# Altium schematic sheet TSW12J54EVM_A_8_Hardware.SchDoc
size 431 x 279 mm; Date: Not shown in title block; ApprovedBy: Not shown in title block; CheckedBy: Not shown in title block; Author: Not shown in title block; CompanyName: Not shown in title block; Engineer: Not shown in title block; Organization: Not shown in title block; Address1: Not shown in title block; Address2: Not shown in title block; Address3: Not shown in title block; Address4: Not shown in title block; DocumentNumber: 8; Revision: Use project parameter SCH_Rev; SheetNumber: 8; SheetTotal: 8; PageSetup: Record=PageOptions¦CenterHorizontal=True¦CenterVertical=True¦PrintScale=1.00¦XCorrection=1.00¦YCorrection=1.00¦PrintKind=0¦BorderSize=5000000¦LeftOffset=0¦BottomOffset=0¦Orientation=2¦PaperLength=1000¦PaperWidth=1000¦Scale=100¦PaperSource=15¦PrintQuality=600¦MediaType=1¦DitherType=10¦PaperKind=Letter¦PrintScaleMode=1
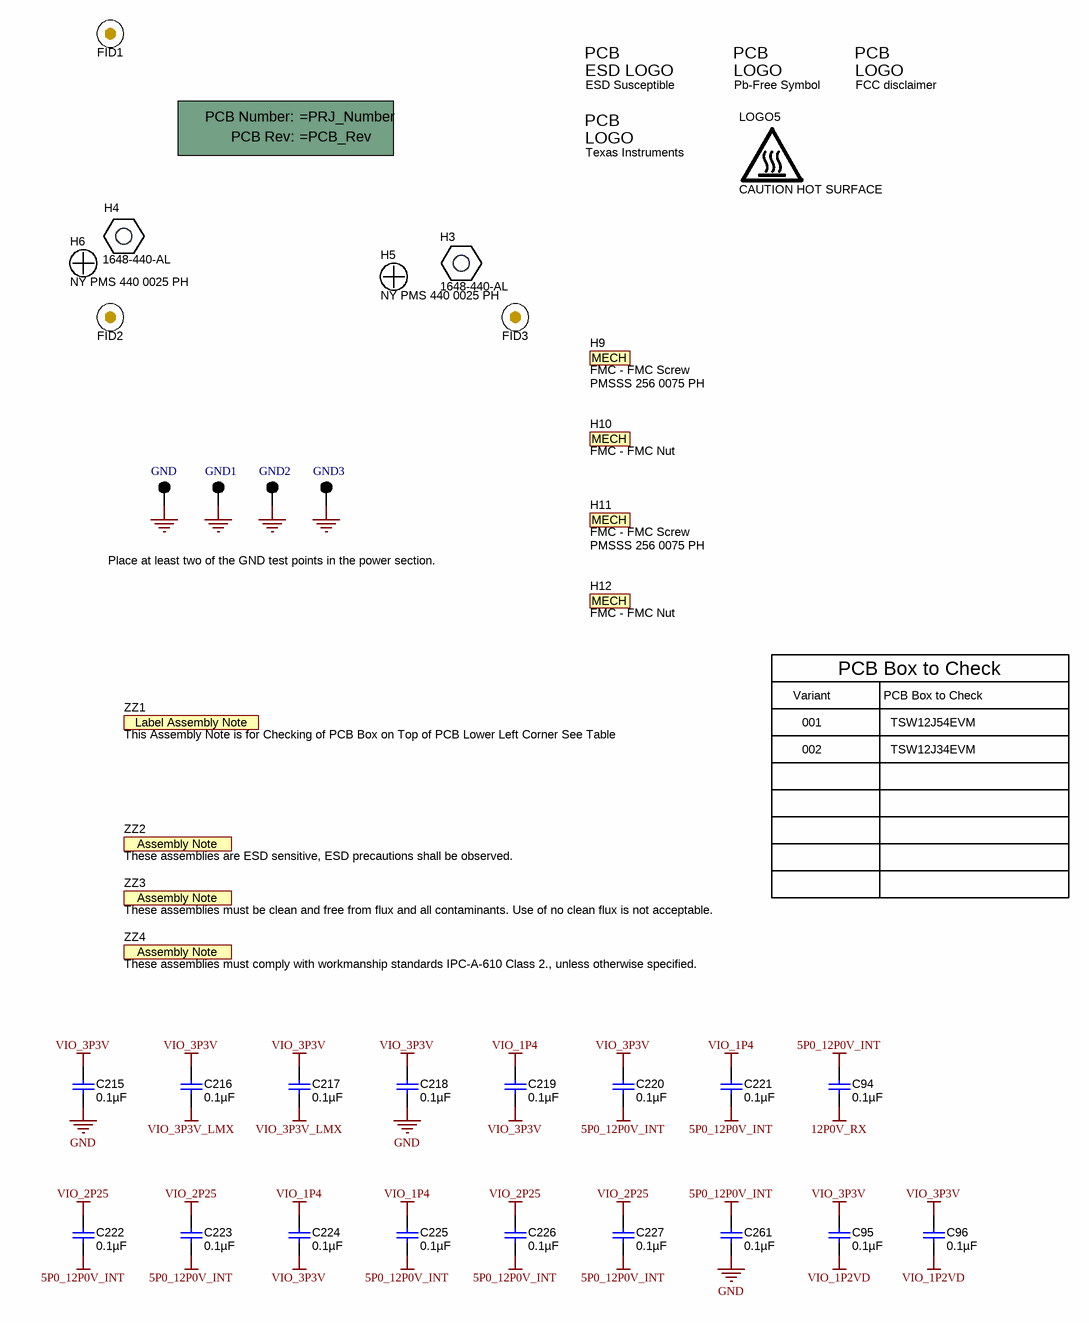
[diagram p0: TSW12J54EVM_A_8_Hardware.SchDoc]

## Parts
!PCB  Printed Circuit Board  (value not drawn)  (mechanical)
C94  ValueDisplayed: 0.1µF  [0402L]  (hidden comment: GRM155R71A104KA01D)
C95  ValueDisplayed: 0.1µF  [0402L]  (hidden comment: GRM155R71A104KA01D)
C96  ValueDisplayed: 0.1µF  [0402L]  (hidden comment: GRM155R71A104KA01D)
C215  ValueDisplayed: 0.1µF  [0402L]  (hidden comment: GRM155R71A104KA01D)
C216  ValueDisplayed: 0.1µF  [0402L]  (hidden comment: GRM155R71A104KA01D)
C217  ValueDisplayed: 0.1µF  [0402L]  (hidden comment: GRM155R71A104KA01D)
C218  ValueDisplayed: 0.1µF  [0402L]  (hidden comment: GRM155R71A104KA01D)
C219  ValueDisplayed: 0.1µF  [0402L]  (hidden comment: GRM155R71A104KA01D)
C220  ValueDisplayed: 0.1µF  [0402L]  (hidden comment: GRM155R71A104KA01D)
C221  ValueDisplayed: 0.1µF  [0402L]  (hidden comment: GRM155R71A104KA01D)
C222  ValueDisplayed: 0.1µF  [0402L]  (hidden comment: GRM155R71A104KA01D)
C223  ValueDisplayed: 0.1µF  [0402L]  (hidden comment: GRM155R71A104KA01D)
C224  ValueDisplayed: 0.1µF  [0402L]  (hidden comment: GRM155R71A104KA01D)
C225  ValueDisplayed: 0.1µF  [0402L]  (hidden comment: GRM155R71A104KA01D)
C226  ValueDisplayed: 0.1µF  [0402L]  (hidden comment: GRM155R71A104KA01D)
C227  ValueDisplayed: 0.1µF  [0402L]  (hidden comment: GRM155R71A104KA01D)
C261  ValueDisplayed: 0.1µF  [0402L]  (hidden comment: GRM155R71A104KA01D)
FID1  Fiducial  [Fiducial10-30]  (value not drawn)
FID2  Fiducial  [Fiducial10-30]  (value not drawn)
FID3  Fiducial  [Fiducial10-30]  (value not drawn)
GND  5011  [Keystone5011]  (value not drawn)
GND1  5011  [Keystone5011]  (value not drawn)
GND2  5011  [Keystone5011]  (value not drawn)
GND3  5011  [Keystone5011]  (value not drawn)
H3  1648-440-AL  [Keystone_1902C]
H4  1648-440-AL  [Keystone_1902C]
H5  NY PMS 440 0025 PH  [NY PMS 440 0025 PH]
H6  NY PMS 440 0025 PH  [NY PMS 440 0025 PH]
H9  FMC - FMC Screw  PartNumber: PMSSS 256 0075 PH  (mechanical)
H10  FMC - FMC Nut  (mechanical)
H11  FMC - FMC Screw  PartNumber: PMSSS 256 0075 PH  (mechanical)
H12  FMC - FMC Nut  (mechanical)
Logo1  ESD Susceptible  [ESD_Overlay_Small]  (no BOM)
Logo2  Texas Instruments  [TI_Symbol_Overlay_Small]  (no BOM)
Logo3  Pb-Free Symbol  [Pb-Free_Overlay_Small]  (no BOM)
Logo4  FCC disclaimer  [FCC_disclaimer]  (no BOM)
LOGO5  CAUTION HOT SURFACE  [IEC_HotSurface_Small]  (no BOM)
ZZ1  This Assembly Note is for Checking of PCB Box on Top of PCB Lower Left Corner See Table  [AssemblyNoteLabel]  (no BOM)
ZZ2  These assemblies are ESD sensitive, ESD precautions shall be observed.  [AssemblyNote]  (no BOM)
ZZ3  These assemblies must be clean and free from flux and all contaminants. Use of no clean flux is not acceptable.  [AssemblyNote]  (no BOM)
ZZ4  These assemblies must comply with workmanship standards IPC-A-610 Class 2., unless otherwise specified.  [AssemblyNote]  (no BOM)

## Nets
5P0_12P0V_INT: C94.1 C220.2 C221.2 C222.2 C223.2 C225.2 C226.2 C227.2 C261.1
12P0V_RX: C94.2
GND: C215.2 C218.2 C261.2 GND.1 GND1.1 GND2.1 GND3.1
VIO_1P2VD: C95.2 C96.2
VIO_1P4: C219.1 C221.1 C224.1 C225.1
VIO_2P25: C222.1 C223.1 C226.1 C227.1
VIO_3P3V: C95.1 C96.1 C215.1 C216.1 C217.1 C218.1 C219.2 C220.1 C224.2
VIO_3P3V_LMX: C216.2 C217.2

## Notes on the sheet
- Place at least two of the GND test points in the power section.
- Variant
- PCB Box to Check
- 001
- 002
- TSW12J54EVM
- TSW12J34EVM

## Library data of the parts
!PCB = PCB: Manufacturer: Any; SymbolCreator: a0412235
C94-C96 C215-C227 C261 = GRM155R71A104KA01D: CAP, CERM, 0.1uF, 10V, +/-10%, X7R, 0402; Manufacturer: MuRata; Polarized: N; CompType: Capacitor; U/M: EA; Cap_F: 0.0000001; Tolerance_%: 10; TaMin_C: -55; TaMax_C: 125; Cap_Case: 0402
FID1-FID3 = Fiducial: Fiducial mark.  There is nothing to buy or mount.; SymbolCreator: codlsc
GND GND1-GND3 = 5011: Test Point, TH, Multipurpose, Black; Manufacturer: Keystone Electronics; CompType: Test Point Loop
H3 H4 = 1902C: Standoff, Round, 3/16"  x 1-3/16"L #4-40 Aluminum; Manufacturer: RAF; CompType: Hardware; U/M: EA
H5 H6 = NY PMS 440 0025 PH: Machine Screw, Round, #4-40 x 1/4, Nylon, Philips panhead; Manufacturer: B&F Fastener Supply; CompType: Hardware; SymbolCreator: codlsc; U/M: EA
H9 H11 = MechPart: MACHINE SCREW PAN PHILLIPS 2-56; Manufacturer: B&F Fastner Supply; SymbolCreator: codlsc; CompType: Mechanical; U/M: EA
H10 H12 = MechPart: HEX NUT 3/16" STN STEEL 2-56; Manufacturer: B & F Fastener Supply; PartNumber: HNSS256; SymbolCreator: codlsc; CompType: Mechanical; U/M: EA
Logo1 = ESD_Susceptible: ESD Susceptible Symbol; SymbolCreator: codlsc
Logo2 = TI_Logo: Texas Instrument Corporate Signature; SymbolCreator: codlsc
Logo3 = Pb-Free: SymbolCreator: a0412235
Logo4 = FCC_disclaimer: SymbolCreator: codlsc
LOGO5 = IEC_HotSurface: IEC 61010-1 Hot Surface Warning; SymbolCreator: a0412235
ZZ1 = AssemblyNoteLabel: SymbolCreator: a0412235
ZZ2-ZZ4 = AssemblyNote: SymbolCreator: codlsc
